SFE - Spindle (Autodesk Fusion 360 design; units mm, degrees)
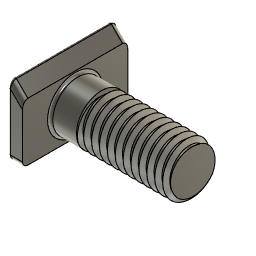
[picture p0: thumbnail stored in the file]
base_feature "Base Feature"
sketch "Sketch2" plane through (63.5, 0, 0) normal (1, 0, 0) x axis (0, 1, 0)
  line L1 (-60.5, 3) -> (-60.5, 33)
  line L2 (60.5, 3) -> (-60.5, 3)
  line L3 (60.5, 33) -> (60.5, 3)
  line L4 (-60.5, 33) -> (60.5, 33)
  line L5 (60.5, 33) -> (-60.5, 33)
  line L6 (60.5, 33) -> (63.5, 33)
  line L7 (63.5, 33) -> (63.5, 3)
  line L8 (60.5, 3) -> (60.5, 33)
  line L9 (60.5, 3) -> (63.5, 3)
  line L10 (60.5, 0) -> (60.5, 3)
  line L11 (-60.5, 3) -> (60.5, 3)
  line L12 (60.5, 0) -> (-60.5, 0)
  line L13 (-60.5, 33) -> (-60.5, 3)
  line L14 (-63.5, 33) -> (-60.5, 33)
  line L15 (-63.5, 3) -> (-63.5, 33)
  line L16 (-63.5, 3) -> (-60.5, 3)
  line L17 (-60.5, 33) -> (-60.5, 3)
  line L18 (-63.5, 33) -> (-60.5, 33)
  line L19 (0, -9.5) -> (0, 45.5)
  line L20 (78, 18) -> (-70, 18)
  line L21 (10, 26) -> (-10, 26)
  line L22 (10, 10) -> (10, 26)
  line L23 (-10, 10) -> (10, 10)
  line L24 (-10, 26) -> (-10, 10)
  line L25 (7.5, 23.5) -> (-7.5, 23.5)
  line L26 (-7.5, 12.5) -> (7.5, 12.5)
  line L27 (-10, 23.5) -> (-7.5, 23.5)
  line L28 (10, 23.5) -> (7.5, 23.5)
  line L29 (10, 12.5) -> (7.5, 12.5)
  line L30 (-10, 12.5) -> (-7.5, 12.5)
  arc A1 centre (60.5, 3) radius 3 clockwise from (63.5, 3) to (60.5, 0)
  arc A2 centre (-60.5, 3) radius 3 clockwise from (-60.5, 0) to (-63.5, 3)
  circle C1 centre (0, 18) radius 15
  circle C2 centre (0, 18) radius 12.5
  circle C3 centre (0, 18) radius 5.25
  circle C4 centre (0, 18) radius 5
  point P29 (0, 18)
  point P41 (-10, 23.5)
  point P42 (10, 23.5)
  point P43 (10, 12.5)
  point P44 (-10, 12.5)
  point P33 (10, 26)
  point P34 (10, 10)
  point P32 (-10, 26)
  point P37 (-7.5, 23.5)
  perpendicular L12 L19
  perpendicular L15 L20
  midpoint L19 P29
  coincident L20 P29
  concentric C1 C3
  horizontal L21
  vertical L22
  horizontal L23
  vertical L24
  symmetric L20 L21 L23
  concentric C1 C4
  coincident L24 P41
  perpendicular L24 L27
  coincident L22 P42
  perpendicular L22 L28
  coincident L22 P43
  perpendicular L22 L29
  coincident L24 P44
  perpendicular L24 L30
  parallel L21 L25
  parallel L23 L26
  dimension "d1" diameter C1 = 30
  dimension "d2" distance L4 L20 = 15
  dimension "d3" = -2.5
  dimension "d4" diameter C3 = 10.5
  dimension "d5" distance P33 P34 = 16
  dimension "d6" distance P32 P33 = 20
  dimension "d7" diameter C4 = 10
  dimension "d8" distance L21 P37 = 2.5
  dimension "d9" distance L23 L30 = 2.5
extrude "Extrude1" sketch "Sketch2" profile of C2 C3 L21 L22 L23 L24 C4 L25 L26 L27 L28 L29 L30 blind 2.5
sketch "Sketch1" plane through (66, 0, 0) normal (1, 0, 0) x axis (0, 1, 0)
  line L1 (10, 26) -> (-10, 26)
  line L2 (10, 10) -> (10, 26)
  line L3 (-10, 10) -> (10, 10)
  line L4 (-10, 26) -> (-10, 10)
  circle C1 centre (0, 18) radius 5.45
  circle C2 centre (0, 18) radius 12.4172
  circle C3 centre (0, 18) radius 5
  point P11 (0, 18)
  point P12 (0, 18)
  coincident P11 P12
  dimension "d174" diameter C3 = 10
extrude "Extrude2" sketch "Sketch1" profile of C3 blind 22
thread "Thread1" ThreadOffset 0 ThreadLength 17
offset_faces "OffsetFaces1" distance -0.175
offset_faces "OffsetFaces2" distance -0.175
combine "Combine1"
fillet "Fillet2" radius 0.2
fillet "Fillet3" radius 1
fillet "Fillet4" radius 0.5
